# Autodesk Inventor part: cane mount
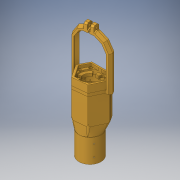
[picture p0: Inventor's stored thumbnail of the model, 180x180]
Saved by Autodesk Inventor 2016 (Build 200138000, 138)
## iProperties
Created: 2015-09
Part Number: cane mount
Material: Generic
Document SubType Name: Modeling
Designer: Z
Density: 1 g/cm^3
Appearance: Brass - Satin
Mass: 133.976 g
Surface Area: 695.269 cm^2
Volume: 133.976 cm^3
Author: Z
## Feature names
1. Extrusion1
2. Extrusion2
3. Extrusion3
4. Extrusion4
5. Extrusion5
6. Hole1
7. Extrusion6
8. Loft1
9. Loft2
10. Fillet2
11. Hole2
12. Circular Pattern1
13. Extrusion11
14. Extrusion12
15. Sweep1
16. Sweep2
17. Loft3
18. Extrusion16
19. Extrusion17
20. Extrusion18
21. Chamfer11
22. Chamfer12
23. Extrusion19
24. Extrusion20
25. Chamfer13
26. Hole3
27. Fillet6
28. Extrusion21
29. Extrusion22
30. Extrusion23
31. Split5
32. Split6
33. Extrusion27
34. Extrusion28
35. Extrusion29
36. Chamfer14
37. Chamfer15
## Parameters: d0 = 34.925 mm, d1 = 6.35 mm, d2 = 50.8 mm, d3 = 0, d4 = 88.9 mm, d5 = 42.2021 mm, d6 = 17.0053 mm, d7 = 23.622 mm, d8 = 31.9659 mm, d9 = 30.6451 mm, d10 = 33.2359 mm, d11 = 15.9258 mm, d12 = 31.9024 mm, d13 = 25.0825 mm, d14 = 1.5367 mm, d15 = 3.175 mm, d16 = 6.35 mm, d17 = 0, d18 = 44.5389 mm, d19 = 44.5389 mm, d20 = 41.91 mm, d21 = 31.75 mm, d22 = 3.175 mm, d23 = 0, d24 = 6.35 mm, d25 = 6.35 mm, d26 = 6.35 mm, d27 = 6.35 mm, d28 = 3.6068 mm, d29 = 19.05 mm, d30 = 6.5024 mm, d31 = 3.175 mm, d32 = 82 deg, d33 = 25.4 mm, d34 = 118 deg, d38 = 360 deg, d40 = 10 deg, d41 = 10 deg, d42 = 10 deg, d43 = 10 deg, d44 = 10 deg, d45 = 10 deg, d46 = 10 deg, d47 = 10 deg, d48 = 6.35 mm, d49 = 0, d50 = 6.35 mm, d51 = 0, d52 = 31.75 mm, d53 = 3.175 mm, d54 = 50.8 mm, d55 = 0, d56 = 0, d57 = 0, d58 = 90 deg, d59 = 0, d60 = 90 deg, d61 = 0, d62 = 90 deg, d63 = 0, d64 = 90 deg, d66 = 6.35 mm, d75 = 120 deg, d76 = 120 deg, d77 = 12.7 mm, d78 = 25.4 mm, d79 = 2.4638 mm, d80 = 5.9944 mm, d81 = 6.5024 mm, d82 = 3.175 mm, d83 = 82 deg, d84 = 8.7884 mm, d85 = 0, d87 = 360 deg, d89 = 1.016 mm, d90 = 1.016 mm, d136 = 0, d137 = 6.35 mm, d138 = 0, d139 = 12.7 mm, d140 = 12.7 mm, d141 = 6.35 mm, d142 = 0, d143 = 12.7 mm, d145 = 6.35 mm, d146 = 6.35 mm, d147 = 0, d148 = 1.5875 mm, d149 = 1.5875 mm, d150 = 82.55 mm, d151 = 88.9 mm, d152 = 99.695 mm, d154 = 78.35128 mm, d155 = 19.05 mm, d156 = 35.56 mm, d157 = 9.525 mm, d158 = 3.175 mm, d159 = 12.7 mm, d160 = 12.7 mm, d161 = 12.7 mm, d162 = 12.7 mm, d163 = 0, d164 = 0, d165 = 0, d166 = 0, d167 = 0, d168 = 90 deg, d169 = 0, d170 = 90 deg, d171 = 12.7 mm, d186 = 3.6576 mm, d187 = 3.175 mm, d188 = 3.175 mm, d189 = 12.7 mm, d190 = 3.175 mm, d191 = 3.175 mm, d192 = 6.35 mm, d193 = 0, d194 = 1.5875 mm, d195 = 1.5875 mm, d196 = 8.89 mm, d197 = 1.27 mm, d198 = 0, d199 = 0, d200 = 3.175 mm, d201 = 0, d202 = 1.27 mm, d203 = 3.175 mm, d204 = 45 deg, d205 = 1.27 mm, d206 = 3.175 mm, d207 = 45 deg, d208 = 6.35 mm, d209 = 6.35 mm, d210 = 1.5875 mm, d211 = 0, d212 = 9.525 mm, d213 = 0, d214 = 3.175 mm, d215 = 3.175 mm, d216 = 45 deg, d217 = 3.048 mm, d218 = 19.05 mm, d219 = 3.81 mm, d220 = 7.62 mm, d221 = 90 deg, d222 = 25.4 mm, d223 = 118 deg, d224 = 3.175 mm, d225 = 3.175 mm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
